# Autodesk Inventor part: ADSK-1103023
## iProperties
Shininess: 41.0
Length Units: 11272
Angle Units: 11279
Time Units: 11290
Mass Units: 11286
Length Display Precision: 4
Angle Display Precision: 2
Compacted: True
Created: 2000-08
Part Number: ADSK-1103023
Document SubType Name: Modeling
Description: METAL TIE
Mass: 0.126378 g
Surface Area: 3.3183 cm^2
Volume: 0.111839 cm^3
Density: 1.13 g/cm^3
Material: Nylon-6/6
Density: 0.0
Volumn: 0.0
Area: 0.0
PropertySet Name: Model Information
Control State: 0
Master: False
Checked Out: False
Author: Autodesk, Inc.
